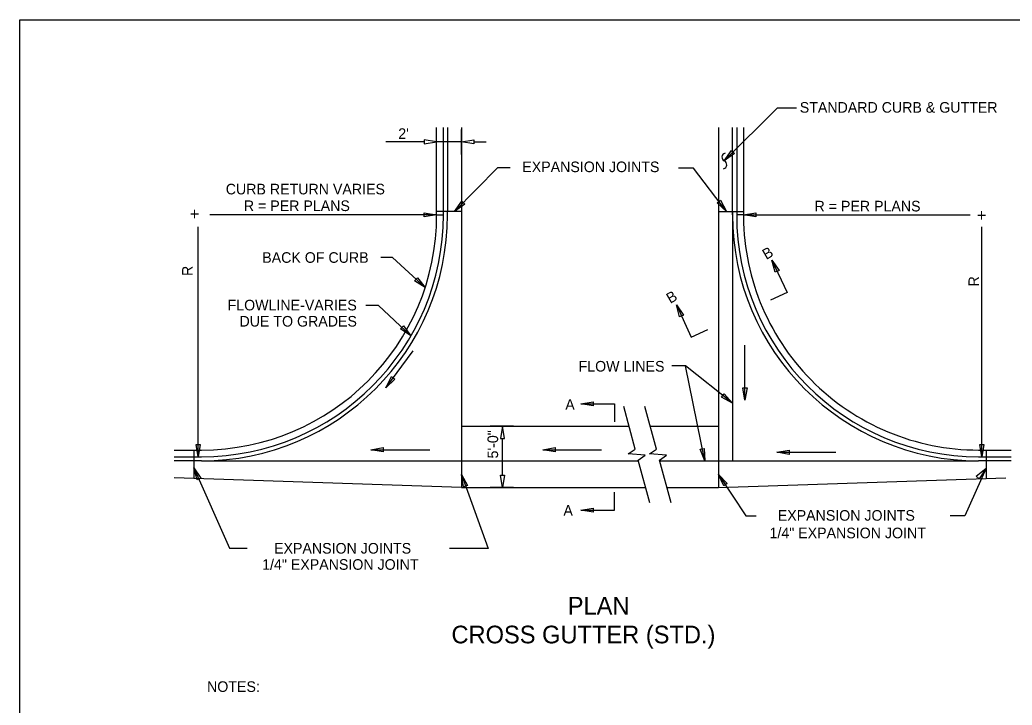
# Model space of a CAD drawing. Extents: x 6712067 to 6713867, y 1867712 to 1869162.
# Drawn here: x 6712067 to 6712628, y 1868774 to 1869162 of the extents above; entities that cross this region are included whole.
import ezdxf

# ---------------------------------------------------------------- set-up
doc = ezdxf.new("R2010")
doc.units = 0
for name, color, linetype in [('Default', 7, 'Continuous'), ('G-MARK', 7, 'Continuous'), ('G-TEXT', 7, 'Continuous'), ('Misc CnstDet(22)', 7, 'Continuous')]:
    doc.layers.add(name, color=color, linetype=linetype)

msp = doc.modelspace()

# ---------------------------------------------------------------- linework, layer by layer
at = {"layer": 'Default'}
msp.add_lwpolyline([(6712066.89, 1869162.31), (6713866.89, 1869162.31), (6713866.89, 1867712.31), (6712066.89, 1867712.31)], close=True, dxfattribs=at)
at = {"layer": 'G-MARK'}
for p, q in [((6712295.68, 1869093.25), (6712274, 1869093.25)), ((6712316.7, 1869093.25), (6712302.69, 1869093.25)), ((6712323.7, 1869093.25), (6712330.71, 1869093.25)), ((6712302.69, 1869051.92), (6712174.45, 1869051.92)), ((6712476.21, 1869051.92), (6712604.44, 1869051.92)), ((6712167.74, 1868915.04), (6712167.74, 1869045.09)), ((6712611.16, 1868915.04), (6712611.16, 1869045.09)), ((6712273.97, 1868954.03), (6712289.44, 1868975.05)), ((6712477.09, 1868947.03), (6712477.09, 1868978.26)), ((6712454.33, 1868912.71), (6712443.53, 1868966.58)), ((6712339.93, 1868904.7), (6712339.93, 1868925.29)), ((6712265.51, 1868919.01), (6712298.78, 1868919.01)), ((6712362.69, 1868919.01), (6712395.96, 1868919.01)), ((6712495.19, 1868917.55), (6712528.46, 1868917.55))]:
    msp.add_line(p, q, dxfattribs=at)
for points in [[(6712465.42, 1869082.45), (6712495.49, 1869112.58), (6712506.29, 1869112.58)], [(6712312.79, 1869053.93), (6712337.3, 1869078.65), (6712344.3, 1869078.65)], [(6712466.59, 1869053.93), (6712447.91, 1869078.36), (6712439.45, 1869078.36)], [(6712296.16, 1869010.74), (6712277.76, 1869027.87), (6712271.05, 1869027.87)], [(6712492.33, 1869026.25), (6712500.98, 1869007.95), (6712491.63, 1869003.6)], [(6712288.13, 1868983.46), (6712269.88, 1869000.73), (6712262.59, 1869000.73)], [(6712438.28, 1869001.02), (6712446.74, 1868982.63), (6712456.08, 1868987.01)], [(6712470.08, 1868945.28), (6712443.53, 1868966.58), (6712435.65, 1868966.58)], [(6712384.29, 1868944.99), (6712403.26, 1868944.99), (6712403.26, 1868934.77)], [(6712423.31, 1868888.92), (6712416.76, 1868913.07), (6712420.68, 1868915.84), (6712411.11, 1868916.64), (6712415.03, 1868919.41), (6712408.49, 1868943.51)], [(6712435.35, 1868888.92), (6712428.79, 1868913.07), (6712432.72, 1868915.84), (6712423.15, 1868916.64), (6712427.07, 1868919.41), (6712420.53, 1868943.51)], [(6712165.4, 1868908.8), (6712185.54, 1868863.27), (6712195.46, 1868863.27)], [(6712613.49, 1868908.51), (6712601.41, 1868881.69), (6712593.27, 1868881.65)], [(6712316.7, 1868905), (6712331.76, 1868863.19), (6712310.04, 1868863.19)], [(6712462.2, 1868905), (6712477.68, 1868881.66), (6712483.51, 1868881.66)], [(6712384.29, 1868884.87), (6712403.26, 1868884.87), (6712403.26, 1868895.08)]]:
    msp.add_lwpolyline(points, dxfattribs=at)
at = {"layer": 'G-TEXT'}
for points in [[(6712295.68, 1869094.41), (6712295.68, 1869092.08), (6712302.69, 1869093.25)], [(6712323.7, 1869094.41), (6712323.7, 1869092.08), (6712316.7, 1869093.25)], [(6712471.16, 1869086.63), (6712465.42, 1869082.45), (6712469.49, 1869088.27)], [(6712318.55, 1869058.08), (6712312.79, 1869053.93), (6712316.89, 1869059.73)], [(6712463.26, 1869060.21), (6712466.59, 1869053.93), (6712461.41, 1869058.79)], [(6712295.68, 1869053.09), (6712302.69, 1869051.92), (6712295.68, 1869050.75)], [(6712483.21, 1869050.75), (6712476.21, 1869051.92), (6712483.21, 1869053.09)], [(6712494.27, 1869019.42), (6712492.33, 1869026.25), (6712496.38, 1869020.41)], [(6712291.83, 1869016.37), (6712296.16, 1869010.74), (6712290.23, 1869014.66)], [(6712440.15, 1868994.17), (6712438.28, 1869001.02), (6712442.27, 1868995.15)], [(6712283.85, 1868989.13), (6712288.13, 1868983.46), (6712282.24, 1868987.43)], [(6712279.06, 1868958.98), (6712273.97, 1868954.03), (6712277.18, 1868960.37)], [(6712478.26, 1868954.03), (6712477.09, 1868947.03), (6712475.93, 1868954.03)], [(6712465.34, 1868950.57), (6712470.08, 1868945.28), (6712463.88, 1868948.75)], [(6712391.29, 1868943.82), (6712384.29, 1868944.99), (6712391.29, 1868946.15)], [(6712338.76, 1868925.29), (6712341.09, 1868925.29), (6712339.93, 1868932.29)], [(6712168.9, 1868922.05), (6712167.74, 1868915.04), (6712166.57, 1868922.05)], [(6712272.51, 1868917.84), (6712265.51, 1868919.01), (6712272.51, 1868920.18)], [(6712369.7, 1868917.84), (6712362.69, 1868919.01), (6712369.7, 1868920.18)], [(6712454.1, 1868919.8), (6712454.33, 1868912.71), (6712451.81, 1868919.35)], [(6712502.19, 1868916.39), (6712495.19, 1868917.55), (6712502.19, 1868918.72)], [(6712612.32, 1868922.05), (6712611.16, 1868915.04), (6712609.99, 1868922.05)], [(6712167.17, 1868901.92), (6712165.4, 1868908.8), (6712169.3, 1868902.86)], [(6712607.92, 1868904.1), (6712613.49, 1868908.51), (6712609.65, 1868902.53)], [(6712317.94, 1868898.01), (6712316.7, 1868905), (6712320.14, 1868898.79)], [(6712338.76, 1868904.7), (6712341.09, 1868904.7), (6712339.93, 1868897.69)], [(6712465.09, 1868898.52), (6712462.2, 1868905), (6712467.04, 1868899.81)], [(6712391.29, 1868883.7), (6712384.29, 1868884.87), (6712391.29, 1868886.03)]]:
    msp.add_lwpolyline(points, close=True, dxfattribs=at)
for centre, start, end in [((6712466.43, 1869084.56), 104.0454, 244.5334), ((6712464.42, 1869080.34), 284.0454, 64.5334)]:
    msp.add_arc(centre, 2.34, start, end, dxfattribs=at)
at = {"layer": 'Misc CnstDet(22)'}
for p, q in [((6712302.69, 1869086.07), (6712302.69, 1869100.25)), ((6712308.82, 1869101.47), (6712308.82, 1869053.93)), ((6712316.7, 1869101.47), (6712316.7, 1868897.69)), ((6712316.7, 1869086.07), (6712316.7, 1869100.25)), ((6712462.2, 1869101.47), (6712462.2, 1868897.69)), ((6712302.69, 1869093.25), (6712302.69, 1869093.25)), ((6712302.69, 1869083.61), (6712302.69, 1869083.61)), ((6712316.7, 1869083.61), (6712316.7, 1869083.61)), ((6712316.7, 1869053.93), (6712302.69, 1869053.93)), ((6712462.2, 1869053.93), (6712476.21, 1869053.93)), ((6712470.08, 1869053.93), (6712470.08, 1868912.71)), ((6712302.69, 1869051.92), (6712306.48, 1869051.92)), ((6712476.21, 1869051.92), (6712472.41, 1869051.92)), ((6712316.7, 1868932.29), (6712411.54, 1868932.29)), ((6712346.23, 1868932.29), (6712332.92, 1868932.29)), ((6712339.93, 1868932.29), (6712339.93, 1868932.29)), ((6712348.68, 1868932.29), (6712348.68, 1868932.29)), ((6712423.58, 1868932.29), (6712462.2, 1868932.29)), ((6712165.4, 1868918.84), (6712165.4, 1868902.68)), ((6712613.49, 1868918.84), (6712613.49, 1868902.68)), ((6712169.61, 1868912.71), (6712154.17, 1868912.71)), ((6712169.61, 1868912.71), (6712416.85, 1868912.71)), ((6712428.89, 1868912.71), (6712609.29, 1868912.71)), ((6712316.7, 1868897.69), (6712154.17, 1868903.05)), ((6712462.2, 1868897.69), (6712624.72, 1868903.05)), ((6712316.7, 1868897.69), (6712420.93, 1868897.69)), ((6712346.23, 1868897.69), (6712332.92, 1868897.69)), ((6712348.68, 1868897.69), (6712348.68, 1868897.69)), ((6712432.97, 1868897.69), (6712462.2, 1868897.69))]:
    msp.add_line(p, q, dxfattribs=at)
for points in [[(6712302.69, 1869051.92), (6712302.69, 1869101.47)], [(6712306.48, 1869051.92), (6712306.48, 1869101.47)], [(6712470.08, 1869051.92), (6712470.08, 1869053.93), (6712470.08, 1869101.47)], [(6712472.41, 1869101.47), (6712472.41, 1869051.92)], [(6712476.21, 1869101.47), (6712476.22, 1869053.93)], [(6712308.82, 1869051.92), (6712308.82, 1869053.93)], [(6712154.17, 1868918.84), (6712169.61, 1868918.84)], [(6712609.29, 1868918.84), (6712627.64, 1868918.84)], [(6712154.17, 1868915.04), (6712169.61, 1868915.04)], [(6712609.29, 1868915.04), (6712627.64, 1868915.04)], [(6712627.64, 1868912.71), (6712609.29, 1868912.71)]]:
    msp.add_lwpolyline(points, dxfattribs=at)
for centre, radius, start, end in [((6712609.29, 1869051.92), 133.08, 179.133, 270), ((6712169.61, 1869051.92), 133.08, 270, 0), ((6712169.61, 1869051.92), 136.88, 270, 0), ((6712169.61, 1869051.92), 139.21, 270, 0), ((6712609.29, 1869051.92), 139.21, 180, 270), ((6712609.29, 1869051.92), 136.88, 180, 270)]:
    msp.add_arc(centre, radius, start, end, dxfattribs=at)

# ---------------------------------------------------------------- texts
at = {"layer": 'G-MARK'}
for p in [(6712163, 1869049), (6712608.21, 1869048.24)]:
    msp.add_text('+', height=7, dxfattribs=at).set_placement(p)
at = {"layer": 'Misc CnstDet(22)'}
for s, height, p in [('STANDARD CURB & GUTTER', 6, (6712508.1, 1869109.76)), ("2'", 6, (6712280.96, 1869094.92)), ('EXPANSION JOINTS', 6, (6712351.13, 1869076.11)), ('CURB RETURN VARIES', 6, (6712183.38, 1869063.52)), ('R = PER PLANS', 6, (6712193.62, 1869054.09)), ('R = PER PLANS', 6, (6712516.45, 1869053.88)), ('BACK OF CURB', 6, (6712204.01, 1869024.79)), ('FLOWLINE-VARIES', 6, (6712184.41, 1868997.87)), ('DUE TO GRADES', 6, (6712191.15, 1868988.71)), ('FLOW LINES', 6, (6712382.98, 1868963.25)), ('A', 6, (6712375.46, 1868941.59)), ('A', 6, (6712374.39, 1868881.69)), ('EXPANSION JOINTS', 6, (6712495.65, 1868878.84)), ('1/4" EXPANSION JOINT', 6, (6712491, 1868868.91)), ('EXPANSION JOINTS', 6, (6712210.7, 1868860.23)), ('1/4" EXPANSION JOINT', 6, (6712203.97, 1868851.07)), ('PLAN', 10, (6712376.84, 1868825.74)), ('CROSS GUTTER (STD.)', 10, (6712311.06, 1868809.43)), ('NOTES:', 6, (6712172.79, 1868781.95))]:
    msp.add_text(s, height=height, dxfattribs=at).set_placement(p)
for s, rotation, p in [('B', 30, (6712489.12, 1869026.38)), ('R', 90, (6712164.66, 1869017.34)), ('R', 90, (6712609.53, 1869011.44)), ('B', 30, (6712434.8, 1869001.51)), ('5\'-0"', 90, (6712337.45, 1868914.08))]:
    msp.add_text(s, height=6, rotation=rotation, dxfattribs=at).set_placement(p)

doc.saveas('drawing.dxf')
